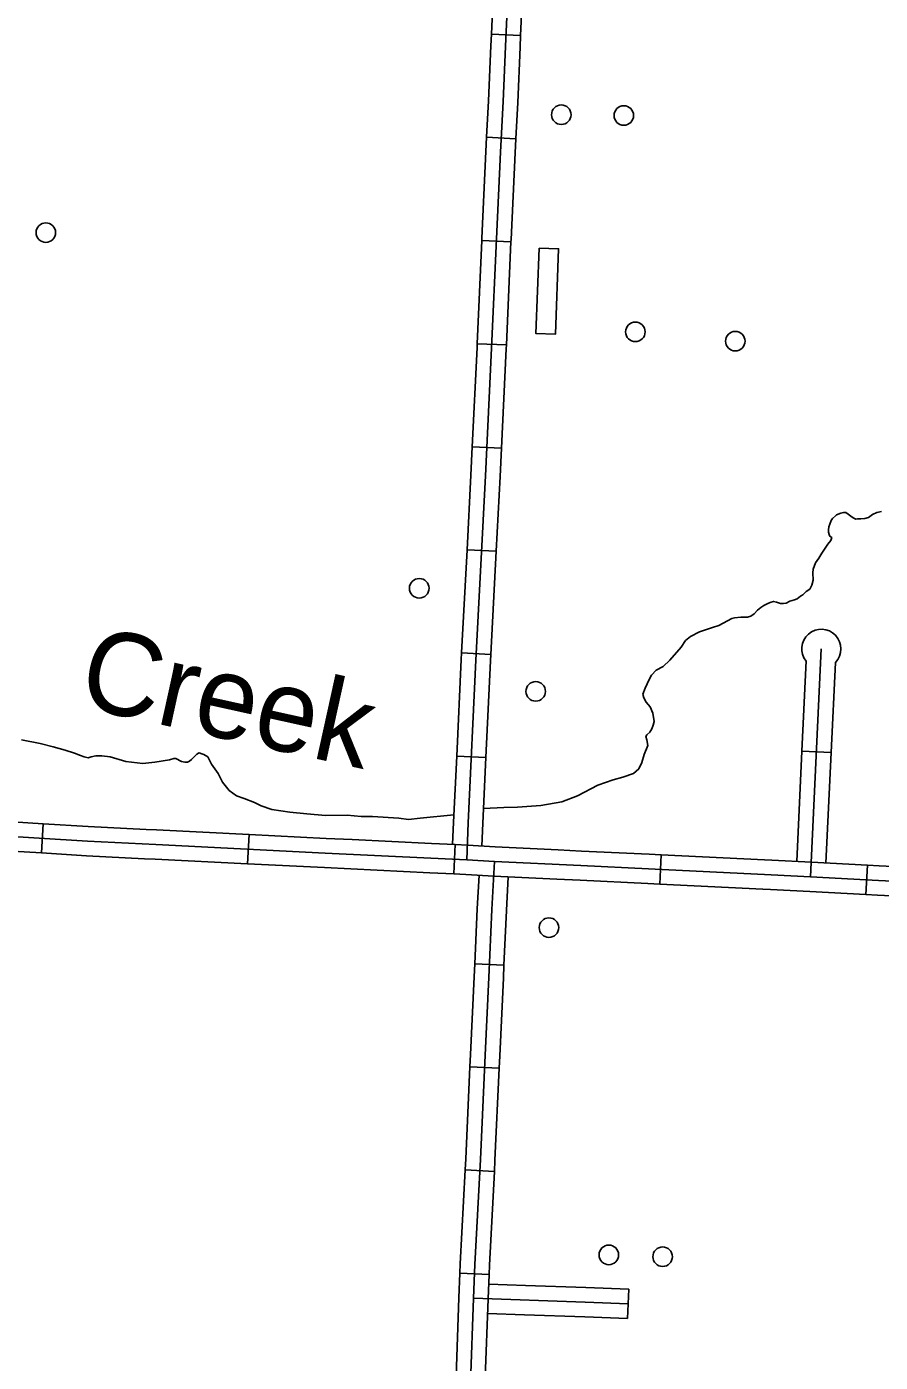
# Model space of a CAD drawing. Extents: x 653372 to 905732, y 627442 to 787275.
# Drawn here: x 698620 to 702988, y 771064 to 777895 of the extents above; entities that cross this region are included whole.
import ezdxf

# ---------------------------------------------------------------- set-up
doc = ezdxf.new("R2010")
doc.units = 0
for name, color, linetype in [('31', 7, 'Continuous'), ('32', 7, 'Continuous'), ('35', 7, 'Continuous'), ('45', 7, 'Continuous'), ('56', 7, 'Continuous')]:
    doc.layers.add(name, color=color, linetype=linetype)

msp = doc.modelspace()

# ---------------------------------------------------------------- linework, layer by layer
at = {"layer": '31'}
for p, q in [((698695.2, 773669.4), (698704.4, 773819.2)), ((698704.4, 773819.2), (698704.4, 773819.2)), ((699758.1, 773763.7), (699750.6, 773613.9)), ((700805.4, 773562.3), (700812.8, 773712.1)), ((701867.5, 773660.1), (701860.2, 773510.3)), ((702914.4, 773456.7), (702922.4, 773606.4)), ((702922.4, 773606.4), (702922.4, 773606.4))]:
    msp.add_line(p, q, dxfattribs=at)
for points in [[(701014, 773626.2), (700871.6, 773634.1), (700687.4, 773643.3), (700148.3, 773669.2), (699281.3, 773712.3), (698930.8, 773730.2), (698462, 773758.9), (698233.7, 773773.6), (698228.6, 773773.8), (698087.3, 773782.3), (697875.7, 773796), (697700.5, 773806.1), (697503.3, 773815.7), (697359.2, 773820), (696949.2, 773844.5), (695998.5, 773896.2), (695143.9, 773943.8), (694614.2, 773970.5)], [(698704.4, 773819.2), (698466.8, 773833.7), (698237.3, 773848.6), (698232, 773848.7), (698177.4, 773852)], [(698704.4, 773819.2), (698935, 773805), (699230.8, 773790)], [(699230.8, 773790), (699285.1, 773787.2), (699758.1, 773763.7)], [(700285.3, 773737.7), (700152, 773744.1), (699758.1, 773763.7)], [(698695.2, 773669.4), (698457.3, 773684), (698230.1, 773698.7), (698225.1, 773698.9), (698168.3, 773702.3)], [(700812.8, 773712.1), (700691, 773718.2), (700285.3, 773737.7)], [(700812.8, 773712.1), (700875.6, 773709), (701017.9, 773701.1), (701340.1, 773685.3)], [(699223.2, 773640.2), (698926.6, 773655.3), (698695.2, 773669.4)], [(699750.6, 773613.9), (699277.5, 773637.4), (699223.2, 773640.2)], [(707137.3, 773324.3), (707071.9, 773326.3), (706597.6, 773346.9), (705986.1, 773379.3), (704937.2, 773433.1), (704816.7, 773437.8), (703992.3, 773479), (703664.4, 773495.8), (702978, 773528.4), (702631.6, 773546.9), (702429.5, 773557.7), (701801.4, 773588.3), (701455.9, 773604.5), (701014, 773626.2)], [(701340.1, 773685.3), (701459.5, 773679.4), (701805, 773663.2), (701867.5, 773660.1)], [(702394.8, 773634.5), (701867.5, 773660.1)], [(702922.4, 773606.4), (702635.6, 773621.8), (702433.3, 773632.6), (702394.8, 773634.5)], [(700278.1, 773587.9), (700144.6, 773594.3), (699750.6, 773613.9)], [(700805.4, 773562.3), (700683.7, 773568.4), (700278.1, 773587.9)], [(701332.7, 773535.5), (701010.1, 773551.3), (700867.7, 773559.2), (700805.4, 773562.3)], [(702922.4, 773606.4), (702981.8, 773603.3), (703449.4, 773581.1)], [(701860.2, 773510.3), (701797.9, 773513.3), (701452.3, 773529.6), (701332.7, 773535.5)], [(702387.5, 773484.7), (701860.2, 773510.3)], [(702914.4, 773456.7), (702627.6, 773472), (702425.7, 773482.8), (702387.5, 773484.7)], [(703442.3, 773431.3), (702974.2, 773453.5), (702914.4, 773456.7)]]:
    msp.add_lwpolyline(points, dxfattribs=at)
at = {"layer": '32'}
for p, q in [((701147.8, 777849.8), (700998, 777856.7)), ((701123.2, 777321.8), (700973.4, 777329.9)), ((701098.3, 776795.1), (700948.4, 776801.7)), ((701075.2, 776267.6), (700925.3, 776274.2)), ((701050.1, 775739.9), (700900.3, 775747.1)), ((701023.2, 775212.3), (700873.4, 775220.1)), ((700995.5, 774685), (700845.7, 774692.9)), ((702586.6, 774189.9), (702736.4, 774182.9)), ((700970.4, 774158), (700820.6, 774165.1)), ((700912.5, 773102.3), (701062.4, 773095.6)), ((700887.9, 772574.9), (701037.7, 772568.1)), ((700863.5, 772048.1), (701013.3, 772040.1)), ((700836.1, 771519.6), (700986, 771514))]:
    msp.add_line(p, q, dxfattribs=at)
for points in [[(700871.6, 773634.1), (700879.5, 773824.3), (700918.9, 774655.2), (700968.3, 775598), (700999.4, 776251), (701023.9, 776811), (701044.4, 777253.7), (701058.4, 777512.2), (701070.2, 777793.6), (701092.7, 778287.7), (701108.1, 778593.8), (701124.3, 778891.4)], [(700998, 777856.7), (701017.8, 778291.3), (701022.5, 778384.4)], [(701147.8, 777849.8), (701167.6, 778284.1), (701172.3, 778376.9)], [(700973.4, 777329.9), (700983.5, 777515.8), (700995.3, 777796.9), (700998, 777856.7)], [(701123.2, 777321.8), (701133.3, 777508.6), (701145.1, 777790.3), (701147.8, 777849.8)], [(700948.4, 776801.7), (700949, 776814.3), (700969.5, 777257.5), (700973.4, 777329.9)], [(701098.3, 776795.1), (701098.8, 776807.6), (701119.3, 777249.9), (701123.2, 777321.8)], [(700925.3, 776274.2), (700948.4, 776801.7)], [(701075.2, 776267.6), (701098.3, 776795.1)], [(700900.3, 775747.1), (700924.5, 776254.4), (700925.3, 776274.2)], [(701050.1, 775739.9), (701074.3, 776247.5), (701075.2, 776267.7)], [(700873.4, 775220.1), (700893.4, 775601.8), (700900.3, 775747.1)], [(701023.2, 775212.3), (701043.2, 775594.3), (701050.1, 775739.9)], [(700845.7, 774692.9), (700873.4, 775220.1)], [(700995.5, 774685), (701023.2, 775212.3)], [(700820.6, 774165.1), (700844, 774659), (700845.7, 774692.9)], [(700970.4, 774158), (700993.8, 774651.5), (700995.5, 774685)], [(702608.2, 774651.3), (702586.6, 774189.9)], [(702686.2, 774713.8), (702631.6, 773546.9)], [(702758, 774644.3), (702736.4, 774182.9)], [(702586.6, 774189.9), (702560.2, 773625.8)], [(702736.4, 774182.9), (702710, 773617.8)], [(700799.8, 773712.8), (700804.6, 773827.7), (700820.6, 774165.1)], [(700949.6, 773704.5), (700954.4, 773821), (700970.4, 774158)], [(701014, 773626.2), (700999.9, 773379.7), (700984.5, 773033.3), (700965.7, 772635.5), (700941.5, 772101.7), (700912.9, 771565), (700906.4, 771392), (700890.9, 770958.5), (700888.6, 770848.8), (700885.9, 770696.8), (700885.8, 770550.3), (700884.2, 770473.6), (700883.7, 770374.6), (700882.6, 770296.4), (700876, 770161.4), (700869.4, 769980.7), (700858.8, 769670.5), (700852, 769633.2)], [(700934.8, 773555.5), (700925, 773383.5), (700912.5, 773102.3)], [(701084.6, 773547.7), (701074.8, 773375.9), (701062.4, 773095.6)], [(700912.5, 773102.3), (700909.6, 773036.7), (700890.8, 772639), (700887.9, 772574.9)], [(701062.4, 773095.6), (701059.4, 773029.8), (701040.6, 772632.1), (701037.7, 772568.1)], [(700887.9, 772574.9), (700866.6, 772105.4), (700863.5, 772048.1)], [(701037.7, 772568.1), (701016.4, 772098), (701013.3, 772040.1)], [(700863.5, 772048.1), (700838, 771568.3), (700836.1, 771519.6)], [(701013.3, 772040.1), (700987.8, 771561.6), (700986, 771514)], [(700836.1, 771519.6), (700831.5, 771394.8), (700817.1, 770991.8)], [(700986, 771514), (700981.4, 771389.3), (700967, 770986.4)]]:
    msp.add_lwpolyline(points, dxfattribs=at)
msp.add_arc((702686.2, 774713.8), 100, 315.90865, 218.72867, dxfattribs=at)
at = {"layer": '35'}
for points in [[(702993.6, 775416.7), (702970.8, 775410.3), (702948.4, 775400.2), (702927.7, 775385.9), (702909.7, 775380.5), (702888.1, 775378.1), (702871.4, 775378), (702863.6, 775377.1), (702849.5, 775382.9), (702836.7, 775391.6), (702823.9, 775402.1), (702812.2, 775410.8), (702800.3, 775411.2), (702785.3, 775408.1), (702764.7, 775398.5), (702759.5, 775394.6), (702744.2, 775379.6), (702736.7, 775369.1), (702729, 775350.8), (702725, 775337.2), (702722.2, 775322.4), (702723, 775309.9), (702726.3, 775298.4), (702729, 775289.4), (702739.5, 775282.7), (702735.5, 775267.9), (702718.8, 775248.7), (702706.3, 775228.8), (702689.4, 775203.1), (702673.7, 775177.3), (702656.9, 775153.4), (702644.6, 775121.5), (702642.9, 775102.6), (702644.1, 775065), (702638, 775038.3), (702627.2, 775018.3), (702609, 775007)], [(702609, 775007), (702592.4, 774990.2), (702579.6, 774982.3), (702562.6, 774969.7), (702549.3, 774964.1), (702525.2, 774957.1), (702506.5, 774947.5), (702493.3, 774945.5), (702476.6, 774945.4), (702457.1, 774952), (702441.7, 774956), (702429.1, 774952.9), (702415.3, 774947.9), (702392.2, 774934.9), (702377, 774925.2), (702360.1, 774912.1), (702342.8, 774892.9), (702326.3, 774880.9), (702308.9, 774876), (702291.6, 774876), (702273.7, 774875.3), (702242.6, 774872.7), (702228.2, 774868.9)], [(700958, 773897.1), (701061.9, 773901.4), (701131.1, 773903.2), (701250.3, 773912.1), (701359.3, 773930.9), (701438.9, 773962.1), (701542.7, 774015.9), (701620.3, 774043.3), (701670.7, 774057.8), (701724.9, 774076.3), (701752.5, 774100.5), (701767.9, 774131.7), (701780.6, 774173.5), (701798.3, 774219.1), (701793.4, 774248), (701789.1, 774264.7), (701793.2, 774273), (701808.1, 774287.9), (701819.1, 774303.9), (701825.4, 774322.9), (701830.8, 774341.2), (701824.4, 774383.7), (701811, 774417.6), (701790.6, 774440.3), (701778.8, 774462.8), (701773.6, 774482.1), (701785.1, 774512.5), (701804.6, 774556.1), (701816.8, 774578.7), (701841.5, 774603.9), (701877.6, 774623.9), (701911.2, 774655.6), (701968.9, 774722), (701991.9, 774755.8), (702016.6, 774777.2), (702062.4, 774799.8), (702130.2, 774822.7), (702161.2, 774833.3), (702228.2, 774868.9)], [(700806.3, 773863.8), (700633, 773848), (700574.2, 773839.8), (700524, 773847.1), (700390.2, 773855.3), (700331.1, 773855.6), (700259.7, 773863), (700149.4, 773860.8), (700054.2, 773868.9), (699966.6, 773878.6), (699875, 773892), (699820.8, 773911.3), (699785.9, 773928.3), (699733.5, 773947.5), (699694.1, 773962), (699656.9, 773988.5), (699622, 774031.4), (699600.3, 774076.2), (699566.4, 774124.1), (699546.3, 774161), (699525.8, 774172.5), (699516.9, 774177.3), (699503.5, 774181), (699498.9, 774179.2), (699491, 774174.1), (699478.2, 774162.1), (699462.7, 774146.7), (699453.7, 774139), (699443.8, 774133.1), (699429.6, 774133.5), (699412.1, 774137.6), (699384, 774152.6), (699372.5, 774152), (699351.1, 774145.6), (699275.6, 774133.7), (699215.2, 774126.7), (699128, 774137.3), (699047.4, 774160.9), (699005.1, 774165.7), (698973.3, 774165.8), (698949.3, 774161.2), (698934.1, 774156.4), (698914.8, 774161.4), (698895.5, 774167.2), (698865, 774179.7), (698816.8, 774195.3), (698756.3, 774212.1), (698688.8, 774229.2), (698594.4, 774248.7)]]:
    msp.add_lwpolyline(points, dxfattribs=at)
at = {"layer": '45'}
msp.add_line((701700.7, 771438.2), (701695.3, 771288.3), dxfattribs=at)
for points in [[(701173.1, 771457.3), (700984.2, 771464.2)], [(701700.7, 771438.2), (701480.8, 771446.1), (701173.1, 771457.3)], [(701698, 771363.3), (701478.1, 771371.1), (700906.4, 771392)], [(701167.6, 771307.4), (700978.7, 771314.3)], [(701695.3, 771288.3), (701475.4, 771296.2), (701167.6, 771307.4)]]:
    msp.add_lwpolyline(points, dxfattribs=at)
at = {"layer": '56'}
msp.add_lwpolyline([(701242.2, 776763.3), (701342.1, 776759.6), (701325.9, 776322.4), (701225.9, 776326.1)], close=True, dxfattribs=at)
for centre in [(701355.6, 777445.4), (701675.4, 777441.3), (698718.3, 776842.4), (701734.7, 776334.6), (702245.9, 776287.1), (700628.8, 775023.3), (701224.8, 774495.9), (701292.5, 773287.6), (701599.1, 771613.6), (701874.3, 771604.5)]:
    msp.add_circle(centre, 50, dxfattribs=at)

# ---------------------------------------------------------------- texts
at = {"layer": '35'}
msp.add_text('Creek', height=422.4, rotation=347.58877, dxfattribs=at).set_placement((698871.9, 774421.6))

doc.saveas('drawing.dxf')
